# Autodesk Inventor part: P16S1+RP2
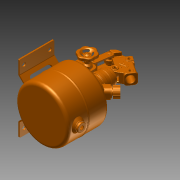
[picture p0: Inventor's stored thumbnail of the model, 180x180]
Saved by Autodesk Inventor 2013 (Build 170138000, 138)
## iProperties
Created: 2015-07
Part Number: P16S1+RP2
Material: Générique
Document SubType Name: Modeling
Designer: OL
Density: 1 g/cm^3
Norme de conversion: STEP AP203
Nom du fichier: P16S1+RP2.STEP
Préprocesseur: SolidWorks 2007
Postprocesseur: Build: 138, Release: 2013 RTM - Date: Thu 03/01/2012
Unités envoyées: millimètre
Incertitude: 1e-05
Author: OL
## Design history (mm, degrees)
node "P16S1+RP21"
feature "Composite1"
body "Srf1"
